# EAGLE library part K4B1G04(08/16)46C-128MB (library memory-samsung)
128Mx 72 - 1GB DDR3 SDRAM Source: http://www.samsung.com/global/business/semiconductor/products/dram/downloads/ddr3_product_guide_july_07.pdf
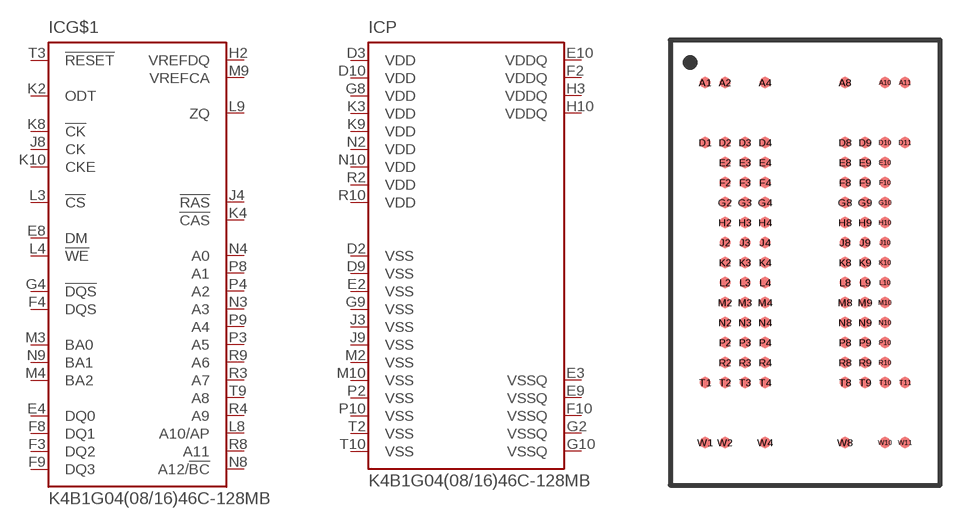
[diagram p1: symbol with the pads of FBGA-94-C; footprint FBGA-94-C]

Designator prefix IC; gates G$1=K4B1G04(08/16)46C-128MB P=K4B1G04(08/16)46C_PWR

## K4B1G04(08/16)46C-128MB (OC_FARNELL: unknown; OC_NEWARK: unknown)  [FBGA-94-C]
D2  P:VSS  in
D3  P:VDD  in
D9  P:VSS  in
D10  P:VDD  in
E2  P:VSS  in
E3  P:VSSQ  in
E4  G$1:DQ0  in
E8  G$1:DM  in
E9  P:VSSQ  in
E10  P:VDDQ  in
F2  P:VDDQ  in
F3  G$1:DQ2  in
F4  G$1:DQS
F8  G$1:DQ1  in
F9  G$1:DQ3  in
F10  P:VSSQ  in
G2  P:VSSQ  in
G4  G$1:!DQS
G8  P:VDD  in
G9  P:VSS  in
G10  P:VSSQ  in
H2  G$1:VREFDQ  in
H3  P:VDDQ  in
H10  P:VDDQ  in
J3  P:VSS  in
J4  G$1:!RAS  in
J8  G$1:CK  in
J9  P:VSS  in
K2  G$1:ODT  in
K3  P:VDD  in
K4  G$1:!CAS  in
K8  G$1:!CK  in
K9  P:VDD  in
K10  G$1:CKE  in
L3  G$1:!CS  in
L4  G$1:!WE  in
L8  G$1:A10/AP  in
L9  G$1:ZQ  in
M2  P:VSS  in
M3  G$1:BA0  in
M4  G$1:BA2  in
M8  G$1:NC  nc
M9  G$1:VREFCA  in
M10  P:VSS  in
N2  P:VDD  in
N3  G$1:A3  in
N4  G$1:A0  in
N8  G$1:A12/!BC  in
N9  G$1:BA1  in
N10  P:VDD  in
P2  P:VSS  in
P3  G$1:A5  in
P4  G$1:A2  in
P8  G$1:A1  in
P9  G$1:A4  in
P10  P:VSS  in
R2  P:VDD  in
R3  G$1:A7  in
R4  G$1:A9  in
R8  G$1:A11  in
R9  G$1:A6  in
R10  P:VDD  in
T2  P:VSS  in
T3  G$1:!RESET  in
T4  G$1:NC  nc
T8  G$1:NC  nc
T9  G$1:A8  in
T10  P:VSS  in

## Footprint FBGA-94-C (pad centres in mm)
94 Ball FBGA for 1Gc C-die (x4/x8) DDR3 SDRAM Source: http://www.samsung.com/global/business/semiconductor/products/dram/downloads/ddr3_product_guide_july_07.pdf
smd 0.45 x 0.45: A1 -4,7.2; A2 -3.2,7.2; A4 -1.6,7.2; A8 1.6,7.2; A10 3.2,7.2; A11 4,7.2; D1 -4,4.8; D2 -3.2,4.8; D3 -2.4,4.8; D4 -1.6,4.8; D8 1.6,4.8; D9 2.4,4.8; D10 3.2,4.8; D11 4,4.8; E2 -3.2,4; E3 -2.4,4; E4 -1.6,4; E8 1.6,4; E9 2.4,4; E10 3.2,4; F2 -3.2,3.2; F3 -2.4,3.2; F4 -1.6,3.2; F8 1.6,3.2; F9 2.4,3.2; F10 3.2,3.2; G2 -3.2,2.4; G3 -2.4,2.4; G4 -1.6,2.4; G8 1.6,2.4; G9 2.4,2.4; G10 3.2,2.4; H2 -3.2,1.6; H3 -2.4,1.6; H4 -1.6,1.6; H8 1.6,1.6; H9 2.4,1.6; H10 3.2,1.6; J2 -3.2,0.8; J3 -2.4,0.8; J4 -1.6,0.8; J8 1.6,0.8; J9 2.4,0.8; J10 3.2,0.8; K2 -3.2,0; K3 -2.4,0; K4 -1.6,0; K8 1.6,0; K9 2.4,0; K10 3.2,0; L2 -3.2,-0.8; L3 -2.4,-0.8; L4 -1.6,-0.8; L8 1.6,-0.8; L9 2.4,-0.8; L10 3.2,-0.8; M2 -3.2,-1.6; M3 -2.4,-1.6; M4 -1.6,-1.6; M8 1.6,-1.6; M9 2.4,-1.6; M10 3.2,-1.6; N2 -3.2,-2.4; N3 -2.4,-2.4; N4 -1.6,-2.4; N8 1.6,-2.4; N9 2.4,-2.4; N10 3.2,-2.4; P2 -3.2,-3.2; P3 -2.4,-3.2; P4 -1.6,-3.2; P8 1.6,-3.2; P9 2.4,-3.2; P10 3.2,-3.2; R2 -3.2,-4; R3 -2.4,-4; R4 -1.6,-4; R8 1.6,-4; R9 2.4,-4; R10 3.2,-4; T1 -4,-4.8; T2 -3.2,-4.8; T3 -2.4,-4.8; T4 -1.6,-4.8; T8 1.6,-4.8; T9 2.4,-4.8; T10 3.2,-4.8; T11 4,-4.8; W1 -4,-7.2; W2 -3.2,-7.2; W4 -1.6,-7.2; W8 1.6,-7.2; W10 3.2,-7.2; W11 4,-7.2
